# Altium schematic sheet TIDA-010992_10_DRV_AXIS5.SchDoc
size 431 x 279 mm; Date: Not shown in title block; ApprovedBy: Not shown in title block; CheckedBy: Not shown in title block; Author: Not shown in title block; CompanyName: Not shown in title block; Engineer: Not shown in title block; Organization: Not shown in title block; Address1: Not shown in title block; Address2: Not shown in title block; Address3: Not shown in title block; Address4: Not shown in title block; DocumentNumber: 10; Revision: Use project parameter SCH_Rev; SheetNumber: 10; SheetTotal: 13; PageSetup: Record=PageOptions¦CenterHorizontal=True¦CenterVertical=True¦PrintScale=1.00¦XCorrection=1.00¦YCorrection=1.00¦PrintKind=0¦BorderSize=5000000¦LeftOffset=0¦BottomOffset=0¦Orientation=2¦PaperLength=1000¦PaperWidth=1000¦Scale=100¦PaperSource=15¦PrintQuality=600¦MediaType=1¦DitherType=10¦PaperKind=Letter¦PrintScaleMode=1
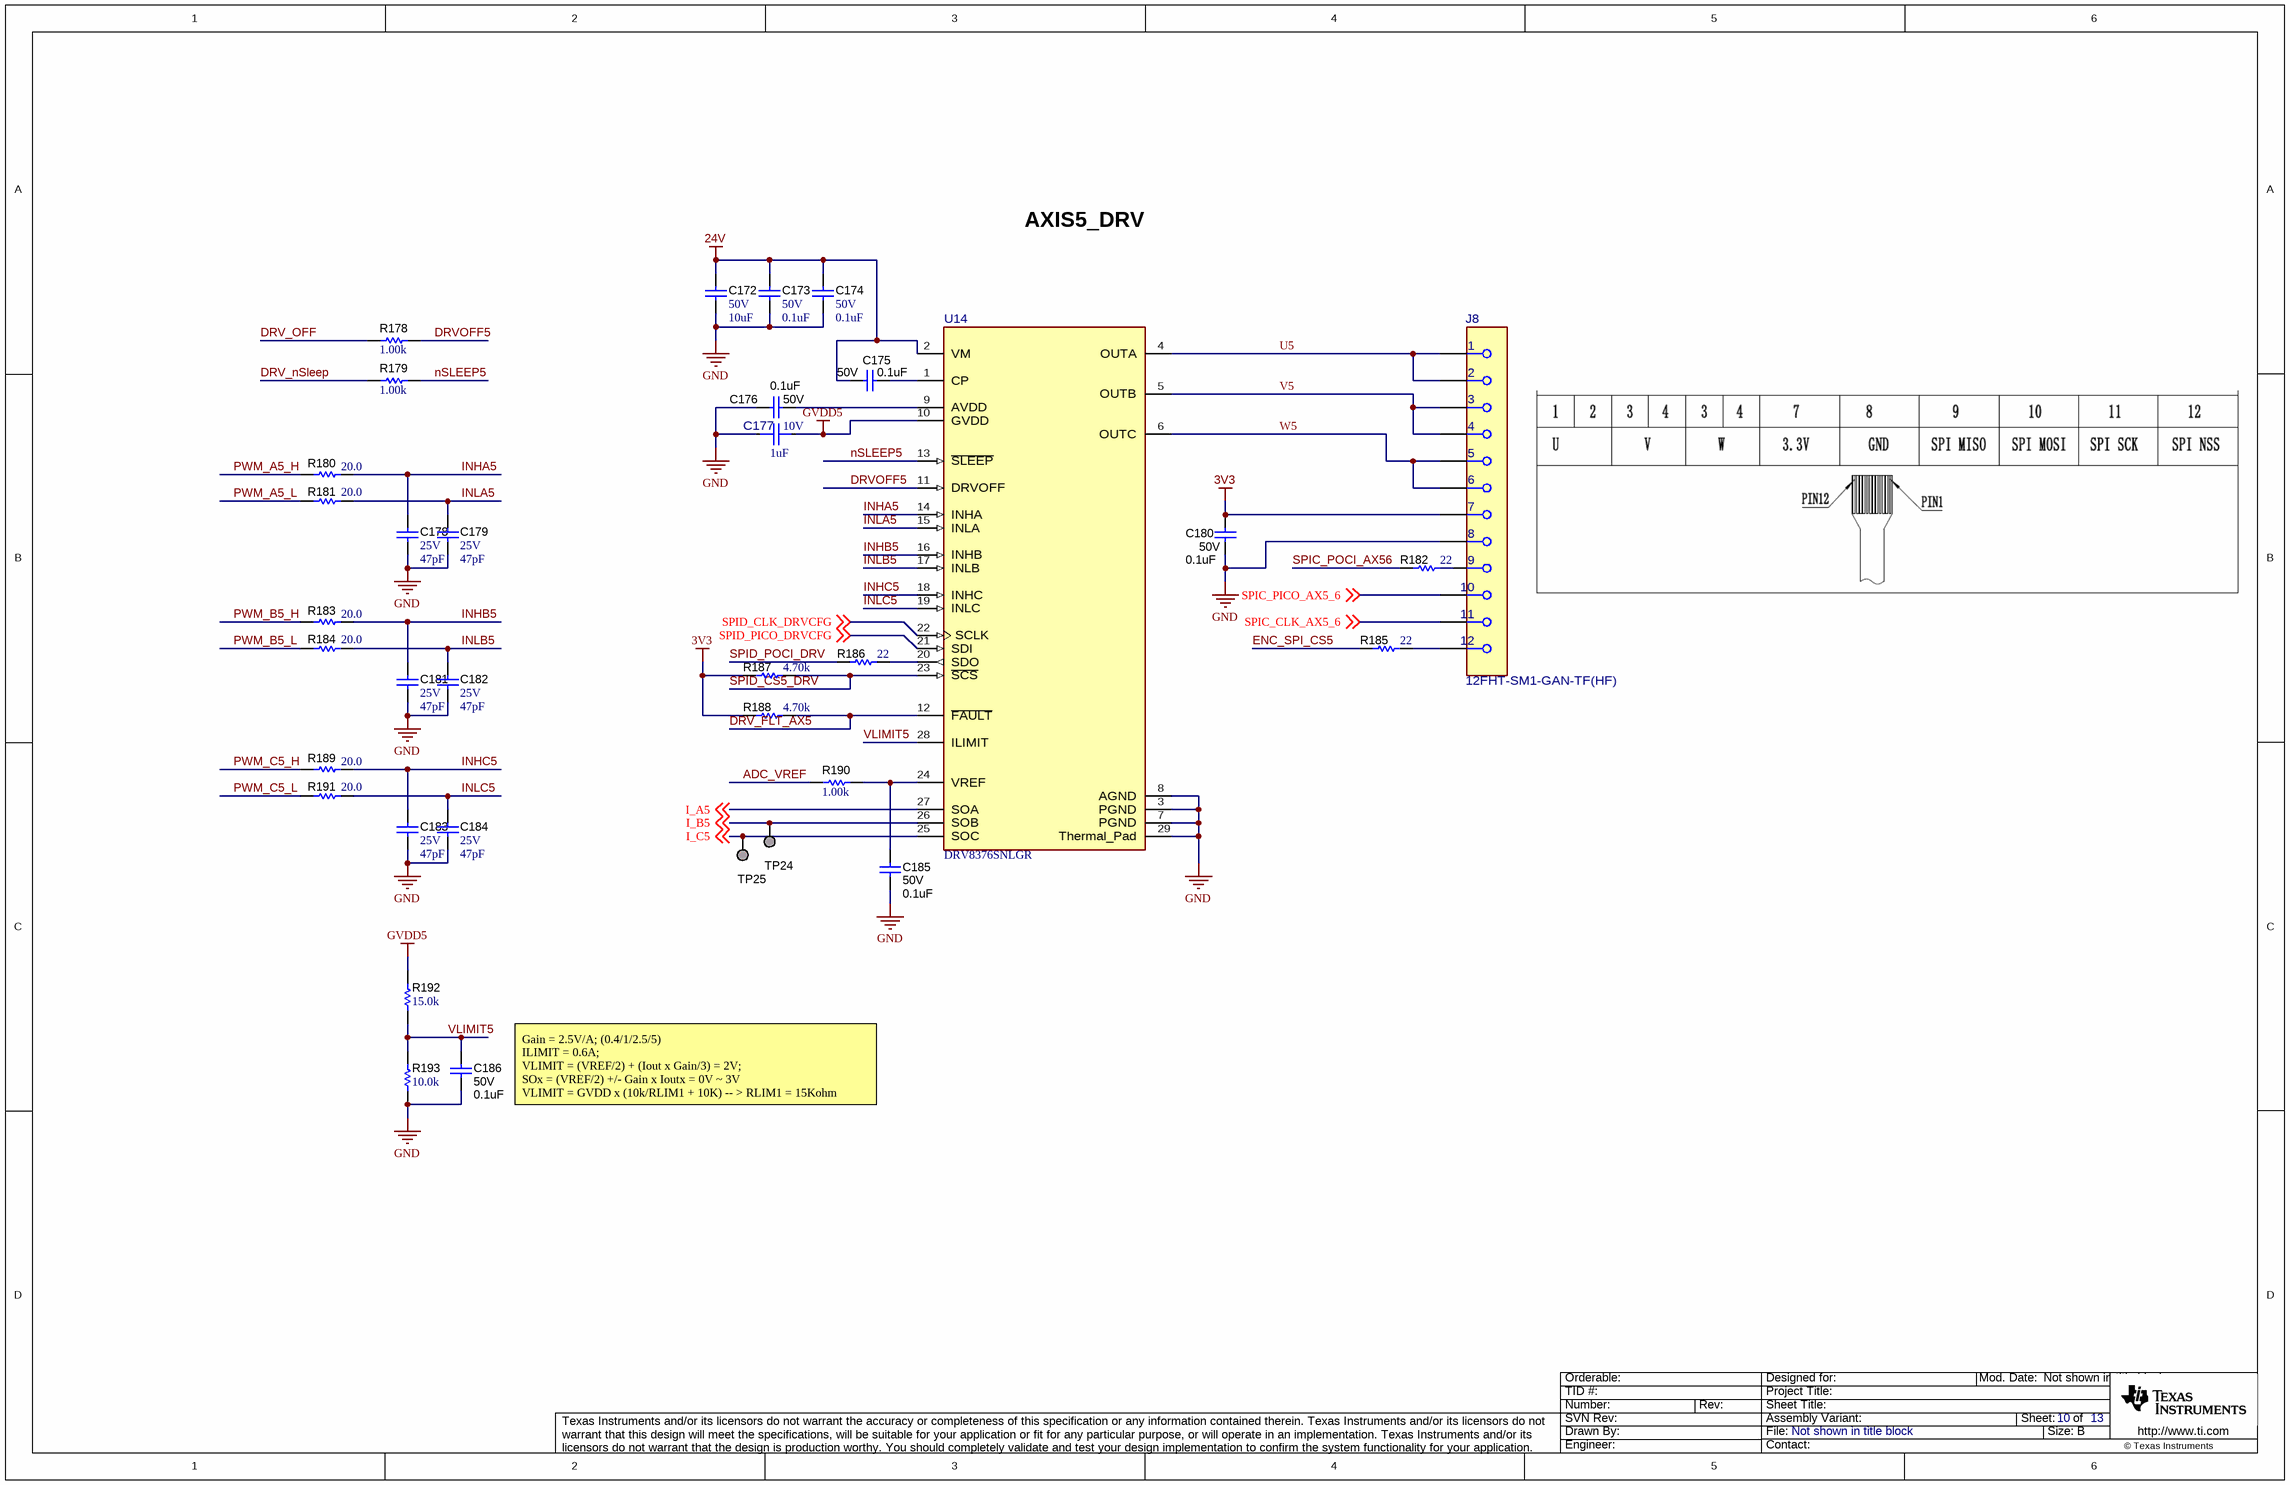
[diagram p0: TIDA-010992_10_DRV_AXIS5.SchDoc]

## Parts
C172  VDC_V: 50V  ValueDisplayed: 10uF  [1206_180]  (hidden comment: CL31B106KBHNNNE)
C173  VDC_V: 50V  ValueDisplayed: 0.1uF  [0402]  (hidden comment: C1005X7R1H104K050BE)
C174  VDC_V: 50V  ValueDisplayed: 0.1uF  [0402]  (hidden comment: C1005X7R1H104K050BE)
C175  VDC_V: 50V  ValueDisplayed: 0.1uF  [0402]  (hidden comment: CGA2B3X7R1H104M050BB)
C176  VDC_V: 50V  ValueDisplayed: 0.1uF  [0402]  (hidden comment: CGA2B3X7R1H104M050BB)
C177  VDC_V: 10V  ValueDisplayed: 1uF  [FP-GMC04X7R105K10NT_0402-MFG]  (hidden comment: GMC04X7R105K10NT)
C178  VDC_V: 25V  ValueDisplayed: 47pF  [0201_033]  (hidden comment: GRM0335C1E470JA01D)
C179  VDC_V: 25V  ValueDisplayed: 47pF  [0201_033]  (hidden comment: GRM0335C1E470JA01D)
C180  VDC_V: 50V  ValueDisplayed: 0.1uF  [0402]  (hidden comment: CGA2B3X7R1H104M050BB)
C181  VDC_V: 25V  ValueDisplayed: 47pF  [0201_033]  (hidden comment: GRM0335C1E470JA01D)
C182  VDC_V: 25V  ValueDisplayed: 47pF  [0201_033]  (hidden comment: GRM0335C1E470JA01D)
C183  VDC_V: 25V  ValueDisplayed: 47pF  [0201_033]  (hidden comment: GRM0335C1E470JA01D)
C184  VDC_V: 25V  ValueDisplayed: 47pF  [0201_033]  (hidden comment: GRM0335C1E470JA01D)
C185  VDC_V: 50V  ValueDisplayed: 0.1uF  [0402]  (hidden comment: CGA2B3X7R1H104M050BB)
C186  VDC_V: 50V  ValueDisplayed: 0.1uF  [0402]  (hidden comment: CGA2B3X7R1H104M050BB)
J8  12FHT-SM1-GAN-TF(HF)  [FP-12FHT-SM1-GAN-TF(HF)_CONN_FPC_12-MFG]
R178  ValueDisplayed: 1.00k  [0402]  (hidden comment: CRCW04021K00FKED)
R179  ValueDisplayed: 1.00k  [0402]  (hidden comment: CRCW04021K00FKED)
R180  ValueDisplayed: 20.0  [0201_033]  (hidden comment: CRCW020120R0FNED)
R181  ValueDisplayed: 20.0  [0201_033]  (hidden comment: CRCW020120R0FNED)
R182  ValueDisplayed: 22  [0201]  (hidden comment: ERJ-1GNJ220C)
R183  ValueDisplayed: 20.0  [0201_033]  (hidden comment: CRCW020120R0FNED)
R184  ValueDisplayed: 20.0  [0201_033]  (hidden comment: CRCW020120R0FNED)
R185  ValueDisplayed: 22  [0201]  (hidden comment: ERJ-1GNJ220C)
R186  ValueDisplayed: 22  [0201]  (hidden comment: ERJ-1GNJ220C)
R187  ValueDisplayed: 4.70k  [0201]  (hidden comment: RC0201FR-7D4K7L)
R188  ValueDisplayed: 4.70k  [0201]  (hidden comment: RC0201FR-7D4K7L)
R189  ValueDisplayed: 20.0  [0201_033]  (hidden comment: CRCW020120R0FNED)
R190  ValueDisplayed: 1.00k  [0402]  (hidden comment: CRCW04021K00FKED)
R191  ValueDisplayed: 20.0  [0201_033]  (hidden comment: CRCW020120R0FNED)
R192  ValueDisplayed: 15.0k  [0402]  (hidden comment: RC0402FR-0715KL)
R193  ValueDisplayed: 10.0k  [0402L]  (hidden comment: CRCW040210K0FKED)
TP24  TP_SM_1MM  [TP_SM_1MM]  (value not drawn)  (no BOM)
TP25  TP_SM_1MM  [TP_SM_1MM]  (value not drawn)  (no BOM)
U14  DRV8376SNLGR  [NLG0028A-MFG]

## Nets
3V3: C180.2 J8.7 R187.2 R188.2
24V: C172.1 C173.1 C174.1 C175.1 U14.2(VM)
GND: C172.2 C173.2 C174.2 C176.1 C177.1 C178.2 C179.2 C180.1 C181.2 C182.2 C183.2 C184.2 C185.1 C186.1 J8.8 R193.1 U14.3(PGND) U14.7(PGND) U14.8(AGND) U14.29(Thermal_Pad)
GVDD5: C177.2 R192.2 U14.10(GVDD)
ADC_VREF: R190.1
DRV_FLT_AX5: R188.1 U14.12(~{FAULT})
DRV_nSleep: R179.1
DRV_OFF: R178.1
DRVOFF5: R178.2 U14.11(DRVOFF)
ENC_SPI_CS5: R185.1
I_A5: U14.27(SOA) ; off-sheet I_A5
I_B5: TP24.1 U14.26(SOB) ; off-sheet I_B5
I_C5: TP25.1 U14.25(SOC) ; off-sheet I_C5
INHA5: C178.1 R180.2 U14.14(INHA)
INHB5: C181.1 R183.2 U14.16(INHB)
INHC5: C183.1 R189.2 U14.18(INHC)
INLA5: C179.1 R181.2 U14.15(INLA)
INLB5: C182.1 R184.2 U14.17(INLB)
INLC5: C184.1 R191.2 U14.19(INLC)
nSLEEP5: R179.2 U14.13(~{SLEEP})
PWM_A5_H: R180.1
PWM_A5_L: R181.1
PWM_B5_H: R183.1
PWM_B5_L: R184.1
PWM_C5_H: R189.1
PWM_C5_L: R191.1
SPIC_CLK_AX5_6: J8.11 ; off-sheet SPIC_CLK_AX5_6
SPIC_PICO_AX5_6: J8.10 ; off-sheet SPIC_PICO_AX5_6
SPIC_POCI_AX56: R182.1
SPID_CLK_DRVCFG: U14.22(SCLK) ; off-sheet SPID_CLK_DRVCFG
SPID_CS5_DRV: R187.1 U14.23(~{SCS})
SPID_PICO_DRVCFG: U14.21(SDI) ; off-sheet SPID_PICO_DRVCFG
SPID_POCI_DRV: R186.1
U5: J8.1 J8.2 U14.4(OUTA)
V5: J8.3 J8.4 U14.5(OUTB)
VLIMIT5: C186.2 R192.1 R193.2 U14.28(ILIMIT)
W5: J8.5 J8.6 U14.6(OUTC)
NetC175_2: C175.2 U14.1(CP)
NetC176_2: C176.2 U14.9(AVDD)
NetC185_2: C185.2 R190.2 U14.24(VREF)
NetJ8_9: J8.9 R182.2
NetJ8_12: J8.12 R185.2
NetR186_2: R186.2 U14.20(SDO)

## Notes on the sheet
- AXIS5_DRV
- Gain = 2.5V/A; (0.4/1/2.5/5)
  ILIMIT = 0.6A;
  VLIMIT = (VREF/2) + (Iout x Gain/3) = 2V;
  SOx = (VREF/2) +/- Gain x Ioutx = 0V ~ 3V
  VLIMIT = GVDD x (10k/RLIM1 + 10K) -- > RLIM1 = 15Kohm

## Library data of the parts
C172 = CMP-0008802-2: CAP, CERM, 10 uF, 50 V, +/- 10%, X7R, 1206; Manufacturer: Samsung; TaMin_C: -55°C; Polarized: N; SizeAreaWB_mm2: 10.92; Value1: Unknown; U/M: EA; Value: 10uF; TaMax_C: 125°C; SizeZ_mm: 1.8; SizeX_mm: 3.2; SizeY_mm: 1.6; Cap_Case: 1206; SizeArea_mm2: 5.12; Cap_F: 10µF; AEC Category: Q200
C173 C174 = CMP-0064946-2: CAP, CERM, 0.1 uF, 50 V,+/- 10%, X7R, 0402; Manufacturer: TDK; TaMin_C: -55°C; Polarized: N; SizeAreaWB_mm2: 3; Value1: Unknown; U/M: EA; Value: 0.1uF; TaMax_C: 125°C; SizeZ_mm: 0.6; SizeX_mm: 1; SizeY_mm: 0.5; Cap_F: 100nF; AEC Category: Q200
C175 C176 C180 C185 C186 = CMP-0006326-2: CAP, CERM, 0.1 uF, 50 V, +/- 20%, X7R, AEC-Q200 Grade 1, 0402; Manufacturer: TDK; TaMin_C: -55°C; Polarized: N; SizeAreaWB_mm2: 3; Value1: Unknown; U/M: EA; Value: 0.1uF; TaMax_C: 125°C; SizeZ_mm: 0.6; SizeX_mm: 1; SizeY_mm: 0.5; AEC Qualified: Y; Cap_F: 100nF; AEC Category: Q200
C177 = CMP-0093200-1: 1µF ±10% 10V Ceramic Capacitor X7R 0402 (1005 Metric); Manufacturer: Cal-Chip Electronics; TempCo: 15%; SizeZ_mm: 0.6mm; AEC Qualified: No
C178 C179 C181-C184 = CMP-0009662-3: CAP, CERM, 47 pF, 25 V, +/- 5%, C0G/NP0, 0201; Manufacturer: MuRata; TaMin_C: -55°C; Polarized: N; SizeAreaWB_mm2: 2.08; Value1: Unknown; U/M: EA; Value: 47pF; TaMax_C: 125°C; SizeZ_mm: 0.33; SizeX_mm: 0.6; SizeY_mm: 0.3; Cap_Case: 0201; SizeArea_mm2: 0.18; AEC Category: Q200
J8 = CMP-0126588-1: Conn FPC Connector F 12 POS 0.5mm Solder Ver SMD T/R; Manufacturer: JST; ContactFinish: Gold,Nickel; Current_A: 500mA; Voltage_V: 50V; AEC Qualified: No; Conn Gender: Female; Conn Orientation: Vertical; Is Female: yes; SizeZ_mm: 3.3mm; Standoff Height: 0.13mm
R178 R179 R190 = CMP-0026071-3: RES, 1.00 k, 1%, 0.063 W, AEC-Q200 Grade 0, 0402; Manufacturer: Vishay-Dale; Power_W: 63mW; TempCo: 100 ppm/C; Value_Code: 1k00; Value: 1.00k; EIA_Code: E96; Res_ohm: 1k; SizeX_mm: 1; SizeY_mm: 0.5; SizeZ_mm: 0.6; Value2: 0.063W; AEC Qualified: Y; VDC_V: 50V; AEC Category: Q200; AEC Grade: 0
R180 R181 R183 R184 R189 R191 = CMP-0078192-1: RES, 20.0, 1%, 0.05 W, 0201; Manufacturer: Vishay-Dale; Value_Code: 20R0; SizeArea_mm2: 0.18; AEC Qualified: N; AEC Category: Q200; Res_ohm: 20; Value: 20.0; SizeZ_mm: 0.33; EIA_Code: E96; TempCo: 200 ppm/C; Power_W: 50mW; VDC_V: 30V; SizeY_mm: 0.3; Value2: 0.05W; U/M: EA; SizeX_mm: 0.6
R182 R185 R186 = CMP-0027015-3: RES, 22, 5%, 0.05 W, AEC-Q200 Grade 1, 0201; Manufacturer: Panasonic; Power_W: 50mW; TempCo: 200 ppm/C; Value_Code: 22R0; U/M: EA; Value: 22; EIA_Code: E24; SizeX_mm: 0.6; SizeY_mm: 0.3; SizeZ_mm: 0.26; Value2: 0.05W; SizeArea_mm2: 0.18; AEC Qualified: Y; AEC Grade: 1; AEC Category: Q200
R187 R188 = CMP-0028031-1: RES, 4.70 k, 1%, 0.05 W, 0201; Manufacturer: Yageo America; Power_W: 50mW; TempCo: 200 ppm/C; Value_Code: 4k70; U/M: EA; Value: 4.70k; Res_ohm: 4.7k; SizeX_mm: 0.6; SizeY_mm: 0.3; SizeZ_mm: 0.26; Value2: 0.05W; SizeArea_mm2: 0.18; AEC Qualified: N; VDC_V: 25V; AEC Category: Q200
R192 = CMP-0078583-1: RES, 15.0 k, 1%, 0.063 W, 0402; Manufacturer: Yageo America; Power_W: 63mW; Green_Lifecycle: Active; TempCo: 100 ppm/C; Value_Code: 15k0; Green_REACh: Passed; Value: 15.0k; EIA_Code: E96; Res_ohm: 15k; SizeX_mm: 1; SizeY_mm: 0.5; SizeZ_mm: 0.6; Value2: 0.063W; AEC Qualified: N; AEC Category: Q200
R193 = CMP-0025958-3: RES, 10.0 k, 1%, 0.063 W, AEC-Q200 Grade 0, 0402; Manufacturer: Vishay-Dale; Power_W: 63mW; TempCo: 100 ppm/C; Value_Code: 10k0; Value: 10.0k; EIA_Code: E96; Res_ohm: 10k; SizeX_mm: 1; SizeY_mm: 0.5; SizeZ_mm: 0.6; Value2: 0.063W; AEC Qualified: Y; VDC_V: 50V; AEC Category: Q200; AEC Grade: 0
TP24 TP25 = CMP-0003825-1: 1mm Test Point, SMT; Manufacturer: Any
U14 = CMP-0122073-1: Three-Phase Integrated FET Motor Driver; Manufacturer: Texas Instruments; SizeZ_mm: 1mm; AEC Qualified: No; Max Supply Voltage: 65V; Min Supply Voltage: 4.5V; Motor Type: Brushless DC; Nominal Supply Current: 6.6-8.2mA; Number Of Outputs: 3; Standoff Height: 0mm; Switching Frequency: 100kHz; TaMax_C: +125°C; TaMin_C: -40°C; TJmax_C: +150°C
